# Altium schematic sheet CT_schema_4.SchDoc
size 322 x 309 mm
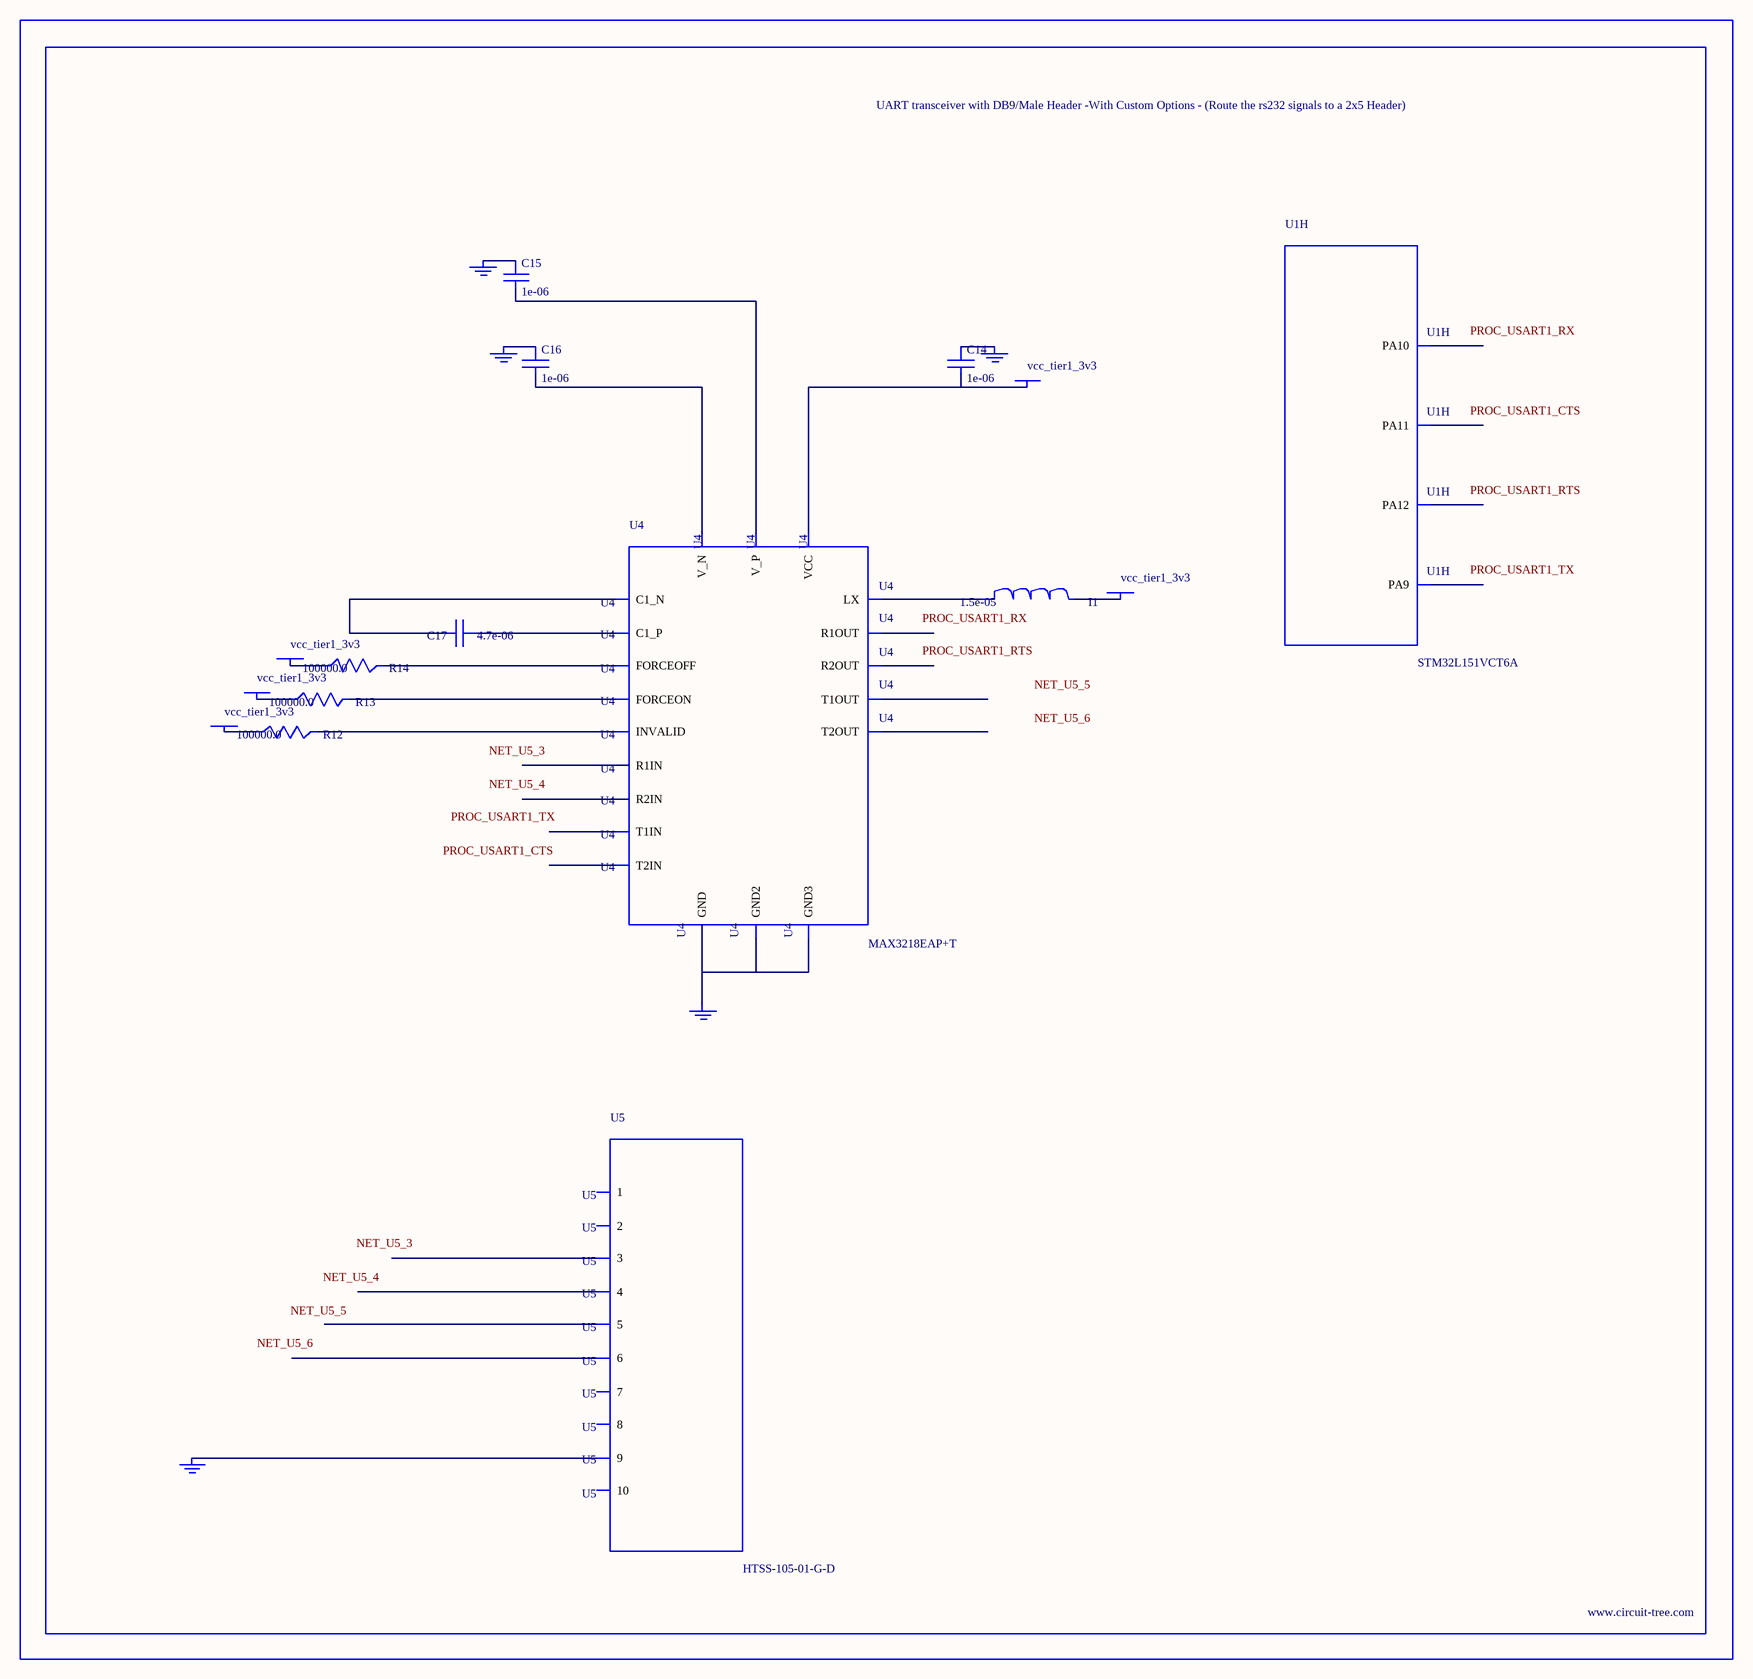
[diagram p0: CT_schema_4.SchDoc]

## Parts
BORDER3  (no value)
C14  1e-06  [C0603]
C15  1e-06  [C0603]
C16  1e-06  [C0603]
C17  4.7e-06  [C0805]
GND_INSTANCE_3_0  (no value)
GND_INSTANCE_3_1  (no value)
GND_INSTANCE_3_2  (no value)
GND_INSTANCE_3_3  (no value)
GND_INSTANCE_3_4  (no value)
I1  1.5e-05  [L1210]
POWER_INSTANCE_3_0  vcc_tier1_3v3
POWER_INSTANCE_3_1  vcc_tier1_3v3
POWER_INSTANCE_3_2  vcc_tier1_3v3
POWER_INSTANCE_3_3  vcc_tier1_3v3
POWER_INSTANCE_3_4  vcc_tier1_3v3
R12  100000.0  [R0603]
R13  100000.0  [R0603]
R14  100000.0  [R0603]
U1  STM32L151VCT6A  [LQFP100]  (part H of 10)
U4  MAX3218EAP+T  [SSOP-20]
U5  HTSS-105-01-G-D  [HTSS-105-01-G-D]

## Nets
NetC14_1: C14.1 GND_INSTANCE_3_0.0(GND)
NetC14_2: C14.2 POWER_INSTANCE_3_4.0(PWR) U4.6(VCC)
NetC15_1: C15.1 GND_INSTANCE_3_2.0(GND)
NetC15_2: C15.2 U4.19(V_P)
NetC16_1: C16.1 GND_INSTANCE_3_1.0(GND)
NetC16_2: C16.2 U4.15(V_N)
NetC17_1: C17.1 U4.18(C1_P)
NetC17_2: C17.2 U4.16(C1_N)
NetGND_INSTANCE_3_3_0: GND_INSTANCE_3_3.0(GND) U4.5(GND) U4.17(GND2) U4.20(GND3)
NetGND_INSTANCE_3_4_0: GND_INSTANCE_3_4.0(GND) U5.9
NetI1_1: I1.1 U4.1(LX)
NetI1_2: I1.2 POWER_INSTANCE_3_0.0(PWR)
NetPOWER_INSTANCE_3_1_0: POWER_INSTANCE_3_1.0(PWR) R12.1
NetPOWER_INSTANCE_3_2_0: POWER_INSTANCE_3_2.0(PWR) R13.1
NetPOWER_INSTANCE_3_3_0: POWER_INSTANCE_3_3.0(PWR) R14.1
NetR12_2: R12.2 U4.2(INVALID)
NetR13_2: R13.2 U4.3(FORCEON)
NetR14_2: R14.2 U4.4(FORCEOFF)

Not connected (* = marked no-connect by the designer): U1 68(PA9) 69(PA10) 70(PA11) 71(PA12); U4 7(T1IN) 8(T2IN) 9(R1OUT) 10(R2OUT) 11(R2IN) 12(R1IN) 13(T2OUT) 14(T1OUT); U5 1 2 3 4 5 6 7 8 10

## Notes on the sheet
- Labels drawn without touching a wire or pin: NET_U5_3, NET_U5_4, NET_U5_5, NET_U5_6, PROC_USART1_CTS, PROC_USART1_RTS, PROC_USART1_RX, PROC_USART1_TX

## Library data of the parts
BORDER3 = BORDER_PAGE3
C14-C16 = C0603C105K3RACTU
C17 = C0805C475K4RACTU
GND_INSTANCE_3_0-GND_INSTANCE_3_4 = GND
I1 = L1210R150MDWIT
POWER_INSTANCE_3_0-POWER_INSTANCE_3_4 = PWR
R12-R14 = RC0603JR-07100KL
